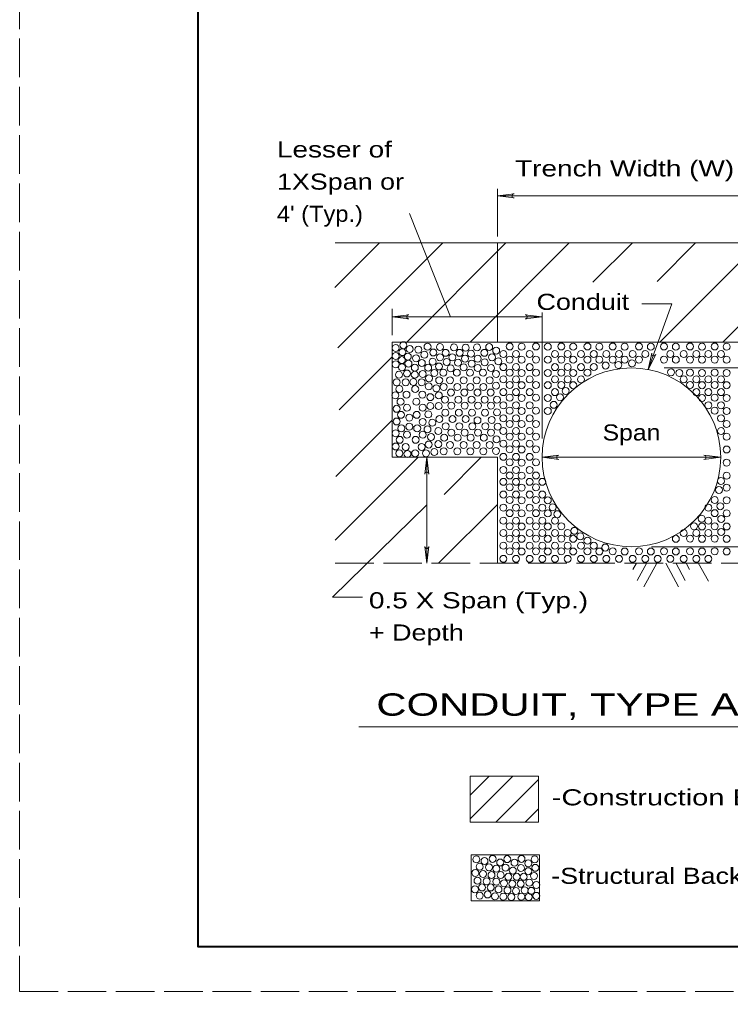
# Model space of a CAD drawing. Extents: x 750.7 to 784.7, y 834.8 to 878.8.
# Drawn here: x 750.65 to 758.61, y 834.78 to 845.66 of the extents above; entities that cross this region are included whole.
import ezdxf

# ---------------------------------------------------------------- set-up
doc = ezdxf.new("R2010")
doc.units = 0
doc.header["$LTSCALE"] = 0.072
doc.linetypes.add('LONG_DASHED', pattern=[7.5, 6, -1.5])
doc.layers.add('1', color=7, linetype='Continuous', lineweight=13)
doc.layers.add('47', color=7, linetype='Continuous', lineweight=13)

msp = doc.modelspace()

# ---------------------------------------------------------------- linework, layer by layer
at = {"layer": '1'}
for p, q in [((755.99883, 843.2315), (755.99883, 843.76325)), ((755.99883, 843.68525), (758.99883, 843.68525)), ((755.47625, 842.33258), (755.01458, 843.48708)), ((754.1815, 842.659), (754.68117, 843.15875)), ((754.18342, 843.15875), (761.30275, 843.15875)), ((754.21533, 841.98575), (755.38825, 843.15875)), ((754.98725, 842.05058), (756.09533, 843.15875)), ((755.69442, 842.05058), (756.80242, 843.15875)), ((755.99883, 843.15875), (755.99883, 842.05058)), ((757.06925, 842.71842), (757.5095, 843.15875)), ((757.78675, 842.72883), (758.21658, 843.15875)), ((757.81558, 842.05058), (758.92367, 843.15875)), ((758.52258, 842.05058), (759.63067, 843.15875)), ((754.82, 842.1275), (754.82, 842.42142)), ((756.49908, 840.97225), (756.49908, 842.38)), ((754.82, 842.33258), (756.49908, 842.33258)), ((754.82, 842.05058), (760.17767, 842.05058)), ((754.2275, 841.29067), (754.82, 841.88325)), ((757.86583, 841.76058), (759.80658, 841.76058)), ((754.19033, 840.54633), (754.82, 841.17608)), ((754.18383, 839.83275), (755.11183, 840.76083)), ((755.20992, 839.5755), (755.20992, 840.76083)), ((755.40233, 840.34433), (755.81883, 840.76083)), ((755.99883, 840.76083), (755.99883, 839.5755)), ((756.49883, 840.76083), (758.49883, 840.76083)), ((755.34075, 839.5755), (755.99883, 840.23358)), ((757.72442, 839.76083), (759.63075, 839.76083)), ((757.55592, 839.57825), (757.51658, 839.50692)), ((757.6725, 839.57967), (757.56467, 839.38417)), ((757.78458, 839.57575), (757.63967, 839.31317)), ((757.8825, 839.57575), (758.02742, 839.31317)), ((757.99458, 839.57967), (758.10242, 839.38417)), ((758.11117, 839.57825), (758.1505, 839.50692)), ((758.2475, 839.57875), (758.36008, 839.37467)), ((754.44783, 837.74617), (760.7465, 837.74617)), ((755.69483, 837.19342), (756.45983, 837.19342)), ((755.69483, 836.67908), (755.69483, 837.19342)), ((755.69483, 836.98017), (755.90808, 837.19342)), ((755.69483, 836.71675), (756.1715, 837.19342)), ((756.45983, 836.67908), (756.45983, 837.19342)), ((755.98325, 836.67908), (756.45983, 837.15567)), ((756.30933, 836.67908), (756.45983, 836.82958)), ((755.69483, 836.67908), (756.45983, 836.67908)), ((755.70733, 836.31525), (756.47233, 836.31525)), ((755.70733, 835.80092), (755.70733, 836.31525)), ((756.47233, 835.80092), (756.47233, 836.31525)), ((755.70733, 835.80092), (756.47233, 835.80092))]:
    msp.add_line(p, q, dxfattribs=at)
at = {"layer": '1', "linetype": 'LONG_DASHED'}
msp.add_line((754.18342, 839.5755), (761.30275, 839.5755), dxfattribs=at)
at = {"layer": '1', "lineweight": 25}
msp.add_line((784.15083, 835.28433), (752.65083, 835.28433), dxfattribs=at)
at = {"layer": '1', "linetype": 'LONG_DASHED'}
msp.add_lwpolyline([(750.65083, 834.78433), (784.65083, 834.78433), (784.65083, 856.78433), (750.65083, 856.78433)], close=True, dxfattribs=at)
at = {"layer": '1', "lineweight": 40}
for points in [[(784.15083, 835.28433), (752.65083, 835.28433), (752.65083, 856.28433), (784.15083, 856.28433)], [(784.15083, 835.28433), (752.65083, 835.28433), (752.65083, 856.28433)]]:
    msp.add_lwpolyline(points, dxfattribs=at)
at = {"layer": '1'}
for points in [[(757.61525, 842.47633), (757.94992, 842.47633), (757.68492, 841.74333)], [(755.99883, 840.76083), (754.82, 840.76083), (754.82, 842.05058)], [(755.20992, 840.22792), (754.1535, 839.19775), (754.49083, 839.19775)]]:
    msp.add_lwpolyline(points, dxfattribs=at)
for centre, radius in [((754.94752, 842.01518), 0.03892), ((754.86218, 841.98318), 0.03892), ((754.93685, 841.93693), 0.03892), ((755.0186, 841.97251), 0.03892), ((755.11452, 841.96543), 0.03892), ((755.1821, 841.90851), 0.03892), ((755.2176, 841.99743), 0.03892), ((755.2816, 841.93343), 0.03892), ((755.35627, 841.99385), 0.03892), ((755.42027, 841.92985), 0.03892), ((755.51268, 841.99026), 0.03892), ((755.5766, 841.92985), 0.03892), ((755.64418, 841.98676), 0.03892), ((755.7046, 841.91918), 0.03892), ((755.7721, 841.99026), 0.03892), ((755.85385, 841.92985), 0.03892), ((755.90718, 841.99385), 0.03892), ((755.98543, 841.95476), 0.03892), ((756.06638, 841.91636), 0.03892), ((756.13741, 842.00072), 0.03892), ((756.20841, 841.91639), 0.03892), ((756.27058, 841.99839), 0.03892), ((756.3593, 841.91636), 0.03892), ((756.43033, 842.00072), 0.03892), ((756.56349, 841.99839), 0.03892), ((756.64338, 841.91636), 0.03892), ((756.71441, 842.00072), 0.03892), ((756.78541, 841.91639), 0.03892), ((756.84758, 841.99839), 0.03892), ((756.9363, 841.91636), 0.03892), ((757.00733, 842.00072), 0.03892), ((757.07833, 841.91639), 0.03892), ((757.14049, 841.99839), 0.03892), ((757.21938, 841.91636), 0.03892), ((757.29041, 842.00072), 0.03892), ((757.36141, 841.91639), 0.03892), ((757.42358, 841.99839), 0.03892), ((757.5123, 841.91636), 0.03892), ((757.58333, 842.00072), 0.03892), ((757.65433, 841.91639), 0.03892), ((757.71649, 841.99839), 0.03892), ((757.86299, 842.00072), 0.03892), ((757.93399, 841.91639), 0.03892), ((757.99616, 841.99839), 0.03892), ((758.08488, 841.91636), 0.03892), ((758.15591, 842.00072), 0.03892), ((758.22691, 841.91639), 0.03892), ((758.28908, 841.99839), 0.03892), ((758.36013, 841.91636), 0.03892), ((758.43116, 842.00072), 0.03892), ((758.50216, 841.91639), 0.03892), ((758.56433, 841.99839), 0.03892), ((754.86218, 841.89426), 0.03892), ((754.86218, 841.80185), 0.03892), ((754.92968, 841.8481), 0.03892), ((754.99727, 841.88718), 0.03892), ((755.00435, 841.80893), 0.03892), ((755.08968, 841.86943), 0.03892), ((755.15368, 841.81601), 0.03892), ((755.27452, 841.83026), 0.03892), ((755.35627, 841.8801), 0.03892), ((755.43093, 841.82676), 0.03892), ((755.49485, 841.8801), 0.03892), ((755.55885, 841.8196), 0.03892), ((755.6371, 841.86585), 0.03892), ((755.71168, 841.80893), 0.03892), ((755.77927, 841.86585), 0.03892), ((755.85743, 841.82318), 0.03892), ((755.93918, 841.8801), 0.03892), ((756.01027, 841.83385), 0.03892), ((756.13741, 841.85422), 0.03892), ((756.27058, 841.85189), 0.03892), ((756.43033, 841.85422), 0.03892), ((756.56349, 841.85189), 0.03892), ((756.71441, 841.85422), 0.03892), ((756.84758, 841.85189), 0.03892), ((757.00733, 841.85422), 0.03892), ((757.14049, 841.85189), 0.03892), ((757.29041, 841.85422), 0.03892), ((757.42358, 841.85189), 0.03892), ((757.50442, 841.81187), 0.03892), ((757.58333, 841.85422), 0.03892), ((757.86299, 841.85422), 0.03892), ((757.99616, 841.85189), 0.03892), ((758.15591, 841.85422), 0.03892), ((758.28908, 841.85189), 0.03892), ((758.43116, 841.85422), 0.03892), ((758.56433, 841.85189), 0.03892), ((754.93327, 841.76626), 0.03892), ((754.98655, 841.69866), 0.03892), ((755.07543, 841.76268), 0.03892), ((755.16405, 841.69425), 0.03892), ((755.22477, 841.76268), 0.03892), ((755.29272, 841.70452), 0.03892), ((755.3456, 841.77693), 0.03892), ((755.3948, 841.70757), 0.03892), ((755.4771, 841.7556), 0.03892), ((755.54572, 841.70757), 0.03892), ((755.62285, 841.76626), 0.03892), ((755.69222, 841.70757), 0.03892), ((755.77927, 841.75918), 0.03892), ((755.83864, 841.70757), 0.03892), ((755.92852, 841.75918), 0.03892), ((755.98514, 841.69424), 0.03892), ((756.06638, 841.76978), 0.03892), ((756.13741, 841.70764), 0.03892), ((756.20841, 841.76981), 0.03892), ((756.27058, 841.70531), 0.03892), ((756.3593, 841.76978), 0.03892), ((756.43033, 841.70764), 0.03892), ((757.49883, 840.76083), 1), ((756.56349, 841.70531), 0.03892), ((756.64338, 841.76978), 0.03892), ((756.71441, 841.70764), 0.03892), ((756.78541, 841.76981), 0.03892), ((756.84758, 841.70531), 0.03892), ((756.9363, 841.76978), 0.03892), ((757.00733, 841.70764), 0.03892), ((757.07833, 841.76981), 0.03892), ((757.21048, 841.78758), 0.03892), ((757.35358, 841.79412), 0.03892), ((757.94289, 841.71203), 0.03892), ((758.03609, 841.70528), 0.03892), ((758.15591, 841.70764), 0.03892), ((758.28908, 841.70531), 0.03892), ((758.43116, 841.70764), 0.03892), ((758.56433, 841.70531), 0.03892), ((754.87106, 841.6001), 0.03892), ((754.89772, 841.68449), 0.03892), ((754.97314, 841.60015), 0.03892), ((755.05972, 841.60235), 0.03892), ((755.07522, 841.68449), 0.03892), ((755.15064, 841.60015), 0.03892), ((755.23281, 841.64452), 0.03892), ((755.34822, 841.62235), 0.03892), ((755.47022, 841.62324), 0.03892), ((755.62114, 841.62324), 0.03892), ((755.76764, 841.62324), 0.03892), ((755.91405, 841.62324), 0.03892), ((756.06638, 841.63211), 0.03892), ((756.20841, 841.63214), 0.03892), ((756.3593, 841.63211), 0.03892), ((756.64338, 841.63211), 0.03892), ((756.78541, 841.63214), 0.03892), ((756.9363, 841.63211), 0.03892), ((758.08488, 841.63211), 0.03892), ((758.22691, 841.63214), 0.03892), ((758.36013, 841.63211), 0.03892), ((758.50216, 841.63214), 0.03892), ((754.90214, 841.52465), 0.03892), ((755.07964, 841.52465), 0.03892), ((755.23056, 841.55577), 0.03892), ((755.31489, 841.53352), 0.03892), ((755.39922, 841.54774), 0.03892), ((755.47914, 841.48557), 0.03892), ((755.55014, 841.54774), 0.03892), ((755.63005, 841.48557), 0.03892), ((755.69664, 841.54774), 0.03892), ((755.77655, 841.48557), 0.03892), ((755.84305, 841.54774), 0.03892), ((755.92297, 841.48557), 0.03892), ((755.98514, 841.56107), 0.03892), ((756.06638, 841.49003), 0.03892), ((756.13741, 841.56997), 0.03892), ((756.20841, 841.49006), 0.03892), ((756.27058, 841.56764), 0.03892), ((756.3593, 841.49003), 0.03892), ((756.43033, 841.56997), 0.03892), ((756.56349, 841.56764), 0.03892), ((756.64338, 841.49003), 0.03892), ((756.71441, 841.56997), 0.03892), ((756.76317, 841.50338), 0.03892), ((756.84758, 841.56764), 0.03892), ((758.15591, 841.56997), 0.03892), ((758.22691, 841.49006), 0.03892), ((758.28908, 841.56764), 0.03892), ((758.36013, 841.49003), 0.03892), ((758.43116, 841.56997), 0.03892), ((758.50216, 841.49006), 0.03892), ((758.56433, 841.56764), 0.03892), ((754.8578, 841.4545), 0.03892), ((754.91547, 841.38257), 0.03892), ((754.98205, 841.46249), 0.03892), ((755.09297, 841.38257), 0.03892), ((755.15955, 841.46249), 0.03892), ((755.24831, 841.4336), 0.03892), ((755.34381, 841.4536), 0.03892), ((755.41255, 841.40565), 0.03892), ((755.56347, 841.40565), 0.03892), ((755.70997, 841.40565), 0.03892), ((755.85639, 841.40565), 0.03892), ((755.99397, 841.40565), 0.03892), ((756.13741, 841.42789), 0.03892), ((756.27058, 841.42556), 0.03892), ((756.43033, 841.42789), 0.03892), ((756.56349, 841.42556), 0.03892), ((756.70108, 841.43236), 0.03892), ((758.28908, 841.42556), 0.03892), ((758.43116, 841.42789), 0.03892), ((758.56433, 841.42556), 0.03892), ((754.87113, 841.3035), 0.03892), ((754.98647, 841.31599), 0.03892), ((755.16397, 841.31599), 0.03892), ((755.24838, 841.33458), 0.03892), ((755.34163, 841.33458), 0.03892), ((755.41697, 841.25915), 0.03892), ((755.48355, 841.33907), 0.03892), ((755.56789, 841.25915), 0.03892), ((755.63447, 841.33907), 0.03892), ((755.71439, 841.25915), 0.03892), ((755.78097, 841.33907), 0.03892), ((755.8608, 841.25915), 0.03892), ((755.92739, 841.33907), 0.03892), ((755.99397, 841.26357), 0.03892), ((756.06638, 841.34353), 0.03892), ((756.13741, 841.28139), 0.03892), ((756.20841, 841.34356), 0.03892), ((756.27058, 841.27906), 0.03892), ((756.3593, 841.34353), 0.03892), ((756.43033, 841.28139), 0.03892), ((756.56349, 841.27906), 0.03892), ((756.63009, 841.34794), 0.03892), ((758.36013, 841.34353), 0.03892), ((758.43116, 841.28139), 0.03892), ((758.50216, 841.34356), 0.03892), ((758.56433, 841.27906), 0.03892), ((754.87113, 841.16141), 0.03892), ((754.91989, 841.23607), 0.03892), ((755.01313, 841.20583), 0.03892), ((755.09739, 841.23607), 0.03892), ((755.16405, 841.157), 0.03892), ((755.22622, 841.24133), 0.03892), ((755.27063, 841.14808), 0.03892), ((755.35047, 841.18808), 0.03892), ((755.49697, 841.18808), 0.03892), ((755.64347, 841.18808), 0.03892), ((755.77655, 841.17475), 0.03892), ((755.9363, 841.17924), 0.03892), ((756.06638, 841.19694), 0.03892), ((756.20841, 841.19697), 0.03892), ((756.3593, 841.19694), 0.03892), ((758.50216, 841.19697), 0.03892), ((754.92439, 841.08507), 0.03892), ((755.01313, 841.10375), 0.03892), ((755.10189, 841.08507), 0.03892), ((755.2173, 841.07266), 0.03892), ((755.33713, 841.05491), 0.03892), ((755.42147, 841.10815), 0.03892), ((755.48355, 841.03715), 0.03892), ((755.57239, 841.10815), 0.03892), ((755.63447, 841.03715), 0.03892), ((755.71889, 841.10815), 0.03892), ((755.78097, 841.03715), 0.03892), ((755.8653, 841.10815), 0.03892), ((755.92739, 841.03715), 0.03892), ((756.00289, 841.10374), 0.03892), ((756.06638, 841.05494), 0.03892), ((756.13741, 841.13481), 0.03892), ((756.20841, 841.05497), 0.03892), ((756.27058, 841.13247), 0.03892), ((756.3593, 841.05494), 0.03892), ((756.43033, 841.13481), 0.03892), ((758.50216, 841.05497), 0.03892), ((758.56433, 841.13247), 0.03892), ((754.86222, 841.02825), 0.03892), ((754.90655, 840.95632), 0.03892), ((754.98647, 841.01407), 0.03892), ((755.08405, 840.95632), 0.03892), ((755.16397, 841.01407), 0.03892), ((755.2573, 840.98825), 0.03892), ((755.40364, 840.9794), 0.03892), ((755.55455, 840.9794), 0.03892), ((755.70105, 840.9794), 0.03892), ((755.84747, 840.9794), 0.03892), ((755.98955, 840.96165), 0.03892), ((756.13741, 840.99281), 0.03892), ((756.27058, 840.99047), 0.03892), ((756.43033, 840.99281), 0.03892), ((758.56433, 840.99047), 0.03892), ((754.86222, 840.88175), 0.03892), ((754.97314, 840.8764), 0.03892), ((755.15064, 840.8764), 0.03892), ((755.23063, 840.90391), 0.03892), ((755.2928, 840.81958), 0.03892), ((755.33713, 840.90833), 0.03892), ((755.39922, 840.8284), 0.03892), ((755.47022, 840.89949), 0.03892), ((755.55014, 840.8284), 0.03892), ((755.62114, 840.89949), 0.03892), ((755.69664, 840.8284), 0.03892), ((755.76764, 840.89949), 0.03892), ((755.84305, 840.8284), 0.03892), ((755.91405, 840.89949), 0.03892), ((755.98514, 840.8329), 0.03892), ((756.06638, 840.91286), 0.03892), ((756.13741, 840.85072), 0.03892), ((756.20841, 840.91289), 0.03892), ((756.27058, 840.84839), 0.03892), ((756.3593, 840.91286), 0.03892), ((756.43033, 840.85072), 0.03892), ((758.56433, 840.84839), 0.03892), ((754.90214, 840.80532), 0.03892), ((754.99314, 840.79869), 0.03892), ((755.07964, 840.80532), 0.03892), ((755.19955, 840.80625), 0.03892), ((756.06638, 840.76636), 0.03892), ((756.20841, 840.76639), 0.03892), ((756.3593, 840.76636), 0.03892), ((756.06638, 840.61978), 0.03892), ((756.13741, 840.70422), 0.03892), ((756.20841, 840.61981), 0.03892), ((756.27058, 840.70189), 0.03892), ((756.3593, 840.61978), 0.03892), ((756.43033, 840.70422), 0.03892), ((758.56433, 840.70189), 0.03892), ((756.13741, 840.55764), 0.03892), ((756.27058, 840.55531), 0.03892), ((756.43033, 840.55764), 0.03892), ((758.50038, 840.49485), 0.03892), ((758.56433, 840.55531), 0.03892), ((756.06638, 840.48661), 0.03892), ((756.13741, 840.42447), 0.03892), ((756.20841, 840.48664), 0.03892), ((756.27058, 840.42214), 0.03892), ((756.3593, 840.48661), 0.03892), ((756.43033, 840.42447), 0.03892), ((756.50133, 840.48664), 0.03892), ((758.47905, 840.39526), 0.03892), ((758.56433, 840.42214), 0.03892), ((756.06638, 840.34453), 0.03892), ((756.13741, 840.28239), 0.03892), ((756.20841, 840.34456), 0.03892), ((756.27058, 840.28006), 0.03892), ((756.3593, 840.34453), 0.03892), ((756.43033, 840.28239), 0.03892), ((756.50133, 840.34456), 0.03892), ((756.56349, 840.28006), 0.03892), ((758.43116, 840.28239), 0.03892), ((758.56433, 840.28006), 0.03892), ((756.06638, 840.19803), 0.03892), ((756.20841, 840.19806), 0.03892), ((756.3593, 840.19803), 0.03892), ((756.50133, 840.19806), 0.03892), ((756.61675, 840.20012), 0.03892), ((758.36013, 840.19803), 0.03892), ((758.49322, 840.21393), 0.03892), ((756.13741, 840.13589), 0.03892), ((756.27058, 840.13356), 0.03892), ((756.43033, 840.13589), 0.03892), ((756.56349, 840.13356), 0.03892), ((756.67, 840.12462), 0.03892), ((758.2846, 840.07367), 0.03892), ((758.43116, 840.13589), 0.03892), ((758.50388, 840.07168), 0.03892), ((758.56433, 840.13356), 0.03892), ((756.06638, 840.05144), 0.03892), ((756.13741, 839.98931), 0.03892), ((756.20841, 840.05147), 0.03892), ((756.27058, 839.98697), 0.03892), ((756.3593, 840.05144), 0.03892), ((756.43033, 839.98931), 0.03892), ((756.50133, 840.05147), 0.03892), ((756.56349, 839.98697), 0.03892), ((756.64338, 840.05144), 0.03892), ((756.71441, 839.98931), 0.03892), ((758.20026, 839.98926), 0.03892), ((758.28908, 839.98697), 0.03892), ((758.36013, 840.05144), 0.03892), ((758.43116, 839.98931), 0.03892), ((758.56433, 839.98697), 0.03892), ((756.06638, 839.91378), 0.03892), ((756.13741, 839.85164), 0.03892), ((756.20841, 839.91381), 0.03892), ((756.27058, 839.84931), 0.03892), ((756.3593, 839.91378), 0.03892), ((756.43033, 839.85164), 0.03892), ((756.50133, 839.91381), 0.03892), ((756.56349, 839.84931), 0.03892), ((756.64338, 839.91378), 0.03892), ((756.71441, 839.85164), 0.03892), ((756.78541, 839.91381), 0.03892), ((756.84758, 839.84931), 0.03892), ((756.86083, 839.93821), 0.03892), ((756.92742, 839.87604), 0.03892), ((757.99616, 839.84931), 0.03892), ((758.08488, 839.91378), 0.03892), ((758.15591, 839.85164), 0.03892), ((758.22691, 839.91381), 0.03892), ((758.28908, 839.84931), 0.03892), ((758.36013, 839.91378), 0.03892), ((758.43116, 839.85164), 0.03892), ((758.50388, 839.92593), 0.03892), ((758.56433, 839.84931), 0.03892), ((756.06638, 839.77169), 0.03892), ((756.20841, 839.77172), 0.03892), ((756.3593, 839.77169), 0.03892), ((756.50133, 839.77172), 0.03892), ((756.64338, 839.77169), 0.03892), ((756.78541, 839.77172), 0.03892), ((756.9363, 839.77169), 0.03892), ((757.00733, 839.82712), 0.03892), ((757.07833, 839.77172), 0.03892), ((757.20708, 839.75171), 0.03892), ((756.06638, 839.62519), 0.03892), ((756.13741, 839.70956), 0.03892), ((756.20841, 839.62522), 0.03892), ((756.27058, 839.70722), 0.03892), ((756.3593, 839.62519), 0.03892), ((756.43033, 839.70956), 0.03892), ((756.50133, 839.62522), 0.03892), ((756.56349, 839.70722), 0.03892), ((756.64338, 839.62519), 0.03892), ((756.71441, 839.70956), 0.03892), ((756.78541, 839.62522), 0.03892), ((756.84758, 839.70722), 0.03892), ((756.9363, 839.62519), 0.03892), ((757.00733, 839.70956), 0.03892), ((757.07833, 839.62522), 0.03892), ((757.14049, 839.70722), 0.03892), ((757.21938, 839.62519), 0.03892), ((757.29041, 839.70956), 0.03892), ((757.36141, 839.62522), 0.03892), ((757.42358, 839.70722), 0.03892), ((757.5123, 839.62519), 0.03892), ((757.58333, 839.70956), 0.03892), ((757.65433, 839.62522), 0.03892), ((757.71649, 839.70722), 0.03892), ((757.79196, 839.62519), 0.03892), ((757.86299, 839.70956), 0.03892), ((757.93399, 839.62522), 0.03892), ((757.99616, 839.70722), 0.03892), ((758.08488, 839.62519), 0.03892), ((758.15591, 839.70956), 0.03892), ((758.22691, 839.62522), 0.03892), ((758.28908, 839.70722), 0.03892), ((758.36013, 839.62519), 0.03892), ((758.43116, 839.70956), 0.03892), ((758.56433, 839.70722), 0.03892), ((755.76437, 836.26247), 0.03892), ((755.94619, 836.26874), 0.03892), ((756.10919, 836.2657), 0.03892), ((756.26905, 836.26875), 0.03892), ((756.41641, 836.2625), 0.03892), ((755.80194, 836.18093), 0.03892), ((755.85528, 836.24367), 0.03892), ((755.90536, 836.17475), 0.03892), ((755.98699, 836.15897), 0.03892), ((756.0308, 836.22804), 0.03892), ((756.09035, 836.17157), 0.03892), ((756.19072, 836.22491), 0.03892), ((756.26282, 836.16529), 0.03892), ((756.34435, 836.21865), 0.03892), ((756.42265, 836.16846), 0.03892), ((755.75177, 836.11197), 0.03892), ((755.83959, 836.09946), 0.03892), ((755.93362, 836.0869), 0.03892), ((756.03707, 836.08687), 0.03892), ((756.12169, 836.06805), 0.03892), ((756.17182, 836.1371), 0.03892), ((756.2158, 836.06808), 0.03892), ((756.29417, 836.0681), 0.03892), ((756.34438, 836.13078), 0.03892), ((756.41022, 836.07746), 0.03892), ((755.74859, 835.92694), 0.03892), ((755.77684, 836.02415), 0.03892), ((755.827, 835.94885), 0.03892), ((755.88034, 836.01785), 0.03892), ((755.92417, 835.94885), 0.03892), ((755.98692, 836.01477), 0.03892), ((756.012, 835.92694), 0.03892), ((756.07467, 835.99594), 0.03892), ((756.16559, 835.98969), 0.03892), ((756.25967, 835.98969), 0.03892), ((756.35684, 836.00219), 0.03892), ((756.43525, 835.9771), 0.03892), ((755.80192, 835.85794), 0.03892), ((755.88967, 835.87044), 0.03892), ((755.97125, 835.84852), 0.03892), ((756.06525, 835.84535), 0.03892), ((756.11234, 835.91752), 0.03892), ((756.15617, 835.84227), 0.03892), ((756.20634, 835.9081), 0.03892), ((756.26592, 835.84535), 0.03892), ((756.30359, 835.91752), 0.03892), ((756.35059, 835.84227), 0.03892), ((756.37875, 835.91127), 0.03892), ((756.43525, 835.85477), 0.03892)]:
    msp.add_circle(centre, radius, dxfattribs=at)
at = {"layer": '47'}
for points in [[(756.18633, 843.70867), (755.99883, 843.68525), (756.18633, 843.66183)], [(755.0075, 842.30917), (754.82, 842.33258), (755.0075, 842.356)], [(756.31158, 842.356), (756.49908, 842.33258), (756.31158, 842.30917)], [(757.77067, 841.91167), (757.68492, 841.74333), (757.72667, 841.92767)], [(755.1865, 840.57333), (755.20992, 840.76083), (755.23333, 840.57333)], [(756.68633, 840.73742), (756.49883, 840.76083), (756.68633, 840.78425)], [(758.31133, 840.78425), (758.49883, 840.76083), (758.31133, 840.73742)], [(755.23333, 839.763), (755.20992, 839.5755), (755.1865, 839.763)]]:
    msp.add_lwpolyline(points, dxfattribs=at)
for centre, start, end in [((756.18634, 843.68526), 90, 270), ((755.00751, 842.33259), 90, 270), ((756.31158, 842.33258), 270, 90), ((757.74866, 841.91967), 160.12536, 340.12536), ((756.68634, 840.76084), 90, 270), ((758.31133, 840.76083), 270, 90), ((755.20992, 840.57333), 0, 180), ((755.20991, 839.76301), 180, 0)]:
    msp.add_arc(centre, 0.02342, start, end, dxfattribs=at)

# ---------------------------------------------------------------- texts
at = {"layer": '1'}
for s, height, width, p in [('Lesser of', 0.18, 1.3, (753.53217, 844.11517)), ('Trench Width (W)', 0.18, 1.3, (756.19767, 843.90283)), ('1XSpan or', 0.18, 1.25, (753.53217, 843.75517)), ("4' (Typ.)", 0.18, 1.1, (753.53217, 843.39517)), ('Conduit', 0.18, 1.25, (756.43742, 842.40992)), ('Span', 0.18, 1.15, (757.17675, 840.949)), ('0.5 X Span (Typ.)', 0.18, 1.3, (754.56192, 839.07108)), ('+ Depth', 0.18, 1.25, (754.56192, 838.71108)), ('CONDUIT, TYPE A & B-FILL', 0.25, 1.4, (754.6445, 837.87008)), ('-Construction Embankment', 0.18, 1.35, (756.60783, 836.86725)), ('-Structural Backfill', 0.18, 1.25, (756.60158, 835.98908))]:
    msp.add_text(s, height=height, dxfattribs=dict(at, width=width)).set_placement(p)

doc.saveas('drawing.dxf')
